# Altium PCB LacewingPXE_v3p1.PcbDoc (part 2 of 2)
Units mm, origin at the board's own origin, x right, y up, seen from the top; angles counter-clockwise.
Board outline 62.74 x 108.59 mm, 2 copper layers (Top Layer, Bottom Layer); 114 components, 91 nets, 539 pads, 84 vias.
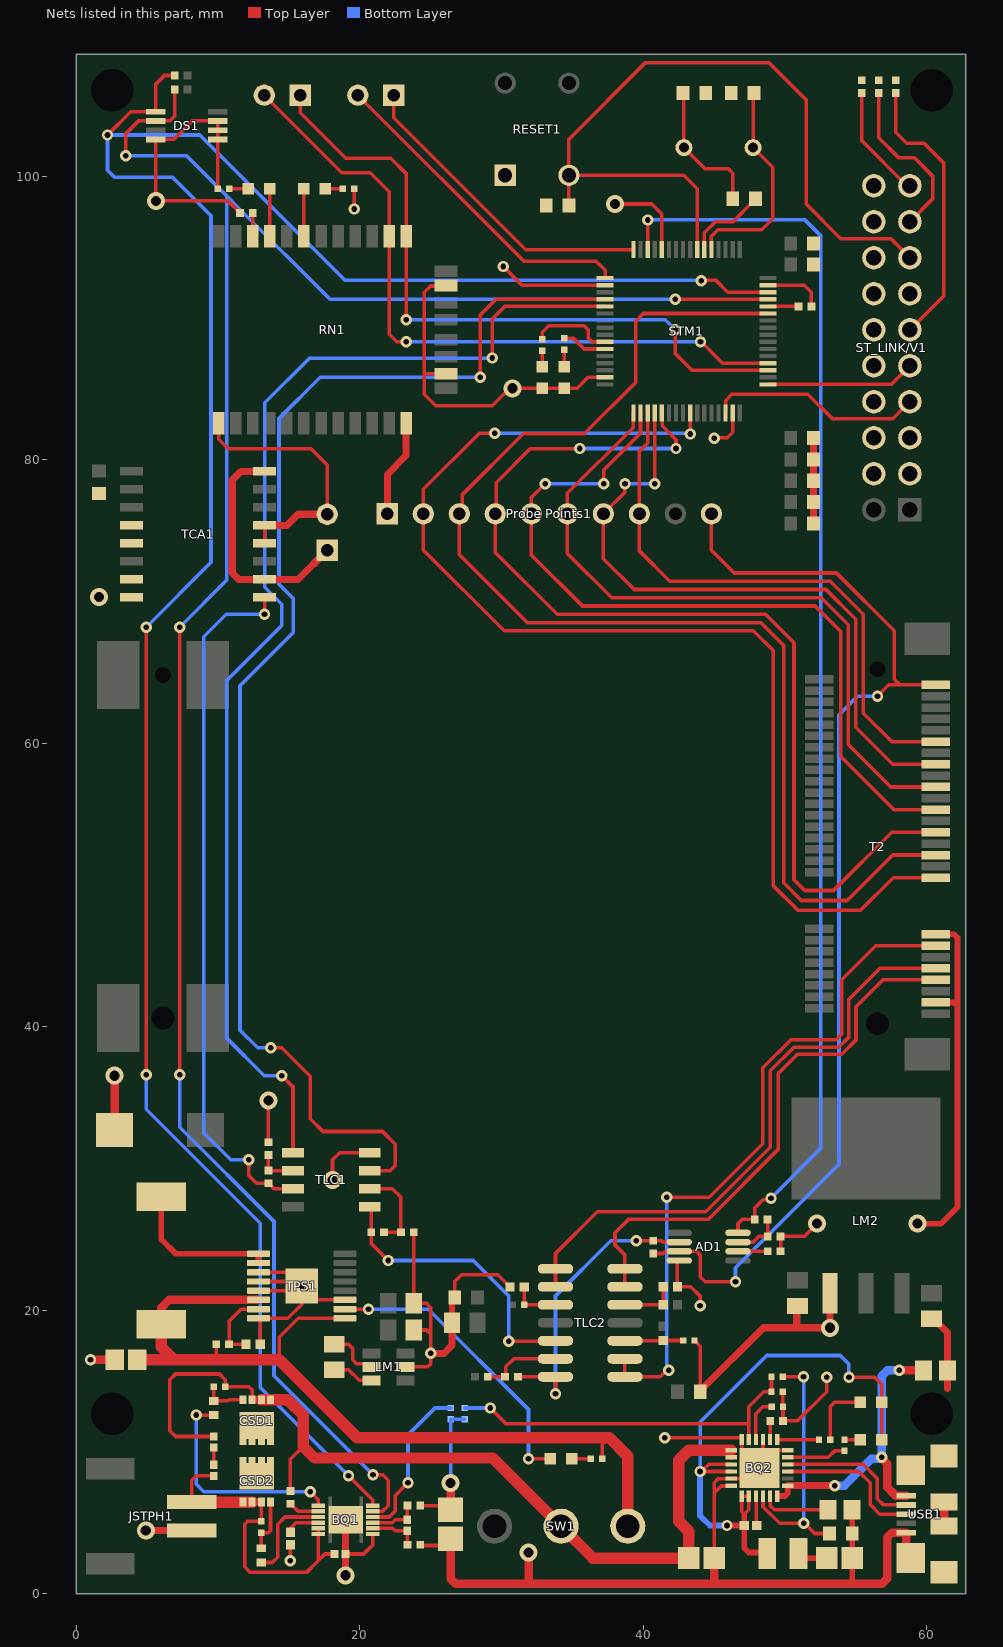
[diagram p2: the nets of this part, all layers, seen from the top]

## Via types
v1: diameter 0.8, hole 0.4, Top Layer to Bottom Layer, 66 vias
v2: diameter 1.27, hole 0.711, Top Layer to Bottom Layer, 18 vias

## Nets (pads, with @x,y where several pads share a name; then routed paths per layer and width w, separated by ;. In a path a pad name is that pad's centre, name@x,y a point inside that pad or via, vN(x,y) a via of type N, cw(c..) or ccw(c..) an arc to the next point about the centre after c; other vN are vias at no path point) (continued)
BAT+: BQ1.11 BQ1.12 C2.2 C11.1 CSD2.1 CSD2.2 CSD2.3 JSTPH1.1 R14.2 | length 23.1
  Top Layer w0.254: JSTPH1.1@8.149,6.461 8.149,8 8.459,8.31 C11.1@9.7,8.31 ; CSD2.3@13.05,6.461 R14.2@13.05,5.1 12.077,5.1 11.877,4.9 11.877,1.896 12.273,1.5 16.241,1.5 17.075,2.334 ; BQ1.11@17.075,4.613 BQ1.12@17.075,4.213 17.075,2.334 ; C2.2@18.21,2.8 17.541,2.8 17.075,2.334
  Top Layer w0.5: CSD2.2@12.4,6.461 CSD2.3@13.05,6.461
  Top Layer w0.8: JSTPH1.1@8.149,6.461 CSD2.1@11.75,6.461 CSD2.2@12.4,6.461
BAT-: BQ1.1 BQ1.13 C1.1 C2.1 JSTPH1.2 R1.2 R3.1 R6.1 R7.2 | length 20.9
  Top Layer w0.254: v1(15.1,2.334) C1.1@15.1,3.46 ; C2.1@18.99,2.8 20.265,2.8 20.925,3.46 BQ1.1@20.925,4.213 ; BQ1.13@18.99,5.203 BQ1.13@19,5.213 ; R6.1@24.255,6.213 26.112,6.213 R1.2@26.4,5.925
  Top Layer w0.5: v2(4.9,4.461) JSTPH1.2@8.149,4.461 ; BQ1.13@18.99,5.203 C2.1@18.99,2.8 19,2.79 v2(19,1.3)
  Top Layer w0.6: R1.2@26.4,5.925 v2(26.4,7.822)
  Bottom Layer w0.254: v2(26.4,7.822) R3.1@26.4,12.3 R7.2@27.4,12.3
BQ_SYS: BQ2.15 BQ2.16 BQ2.19 BQ2.20 C8.2 L1.1 PG.A STAT.A | length 41.9
  Top Layer w0.254: v1(44,8.622) v1@44.105,8.622 ; BQ2.16@46.188,8.622 v1@44.105,8.622 ; BQ2.15@46.188,9.122 44.605,9.122 v1@44.105,8.622 ; v1(54.5,15.266) 56.3,15.266 56.81,14.756 PG.A@56.81,13.5 STAT.A@56.81,10.872 ; 46.938,5.791 BQ2.19@46.938,6.872 BQ2.20@47.438,6.872 47.438,5.931 47.118,5.611 46.938,5.791
  Top Layer w0.4: v1(45.9,4.811) C8.2@47.118,4.811 ; 47.118,5.611 C8.2@47.118,4.811 ; L1.1@48.738,2.836 48.672,2.902 47.438,2.902 47.118,3.222 C8.2@47.118,4.811
  Bottom Layer w0.254: v1(44,8.622) 44,12.1 48.7,16.8 53.888,16.8 54.5,16.188 v1(54.5,15.266)
  Bottom Layer w0.4: v1(44,8.622) 44,5.5 44.689,4.811 v1(45.9,4.811)
GND: "Probe Points1.1" AD1.4 BQ2.6 BQ2.9 BQ2.12 BQ2.17 BQ2.18 BQ2.25 C4.2 C5.1 C6.1 C7.1 C9.1 C12.1 C13.2 C14.1 C15.2 C16.1 C18.2 C19.2 C20.1 C21.1 C22.1 C23.2 C24.2 C25.2 C26.2 C27.2 C28.2 C29.2 C30.2 C31.2 C32.2 D1.C D2.C DS1.4 DS1.5 DS1.6 DS1.7 LM1.2 LM2.1 Peltier1.2 R1.1 R2.1 R4.1 R5.1 R9.1 R18.1 R21.1 R22.1 R24.1 R26.1 R27.1 R28.1 R29.1 R39.1 R40.1 R41.1 R44.1 R46.1 R47.1 R48.1 RESET1.1 RN1.1 RN1.12 RN1.28 RN1.29 ST_LINK/V1.3 ST_LINK/V1.4 ST_LINK/V1.5 ST_LINK/V1.6 ST_LINK/V1.8 ST_LINK/V1.10 ST_LINK/V1.12 ST_LINK/V1.13 ST_LINK/V1.14 ST_LINK/V1.16 ST_LINK/V1.18 ST_LINK/V1.20 STM1.12 STM1.18 STM1.31 STM1.47 STM1.63 T2.3 T2.15 TCA1.4 TCA1.5 TCA1.7 TCA1.8 TCA1.12 TCA1.13 TLC1.4 TPS1.3 TPS1.4 TPS1.5 TPS1.8 TPS1.11 TPS1.PowerPAD USB1.5 USB1.6 USB1.7 USB1.8 USB1.9 USB1.10 USB1.11 | length 297.3
  Top Layer w0.254: R46.1@9.984,99.1 DS1.5@9.984,102.584 DS1.6@9.984,103.234 DS1.7@9.984,103.884 9.976,103.892 8.2,103.892 6.892,102.584 DS1.4@5.616,102.584 v2(5.616,98.243) 10.707,98.243 R48.1@11.55,97.4 ; RN1.1@10.059,82.552 10.059,81.423 10.719,80.764 16.558,80.764 17.7,79.621 Peltier1.2@17.7,76.14 ; TPS1.8@12.85,19.425 14.925,19.425 15.9,20.4 15.9,21.625 16.8,20.725 TPS1.11@18.95,20.725 ; TPS1.5@12.85,21.375 15.575,21.375 v1(15.9,21.7) TPS1.PowerPAD@15.575,22.025 ; TPS1.4@12.85,22.025 TPS1.PowerPAD@15.575,22.025 ; TPS1.3@12.85,22.675 14.925,22.675 TPS1.PowerPAD@15.575,22.025 ; R18.1@12.97,17.6 TPS1.8@12.97,19.327 ; TCA1.12@13.28,74.09 TCA1.13@13.28,75.36 ; R22.1@13.551,31.85 v2(13.551,34.793) ; v2(18.073,29.187) 18.073,30.6 18.578,31.105 TLC1.4@20.712,31.105 ; v1(19.6,97.673) R47.1@19.6,99.1 ; LM1.2@23.223,16 24.791,16 24.999,16.208 v1(24.999,16.95) 24.999,18.299 25,18.3 ; R21.1@23.798,25.5 23.798,20.502 C14.1@23.8,20.5 24.675,20.5 25,20.175 25,18.3 ; C16.1@23.8,18.6 24.7,18.6 25,18.3 ; R5.1@24.255,3.46 24.315,3.4 25.925,3.4 R1.1@26.4,3.875 ; RN1.29@26.082,86.052 24.552,86.052 ; RN1.28@26.082,92.276 26.044,92.238 24.999,92.238 24.552,91.791 24.552,86.052 ; C22.1@26.7,20.9 26.7,22.025 27.175,22.5 29.725,22.5 R27.1@30.6,21.625 ; v1(30.123,93.62) 31.443,92.3 STM1.18@37.3,92.3 ; STM1.31@37.3,85.8 36.1,85.8 35.326,85.026 D2.C@34.418,85.026 D1.C@32.863,85.026 v2(30.756,85.026) 30.57,85.026 29.335,83.792 25.363,83.792 24.552,84.603 24.552,86.052 ; v2(38.008,98.026) 40.591,98.026 41.3,97.317 STM1.12@41.3,94.8 ; v1(41.502,11) 46.915,11 46.938,10.977 BQ2.12@46.938,10.872 46.938,10.122 BQ2.25@48.188,8.872 ; AD1.4@42.524,23.5 42.491,23.5 42.4,23.409 R29.1@42.4,21.65 43.35,21.65 44,21 v1(44,20.3) ; R28.1@43.605,17.861 44.004,17.461 44.004,14.291 C21.1@44.004,14.241 ; C4.2@45,2.511 45,7.1 ; v1(45,81.5) 45.034,81.534 45.912,81.534 46.3,81.922 STM1.47@46.3,83.3 ; BQ2.18@46.188,7.622 46.166,7.6 45.5,7.6 45,7.1 ; BQ2.9@48.438,10.872 BQ2.25@48.438,9.122 ; STM1.63@48.8,92.3 51.35,92.3 51.85,91.8 R44.1@51.85,90.8 ; R24.1@49.676,24.15 R26.1@49.676,25.2 51.337,25.2 v2(52.237,26.1) ; R4.1@49.838,14.247 49.844,14.241 49.844,13.199 R9.1@49.849,13.193 ; R9.1@49.849,13.193 R2.1@49.85,12.19 50.872,12.19 52.928,14.245 v1(52.928,15.266) ; BQ2.6@50.188,10.122 49.438,10.122 BQ2.25@48.438,9.122 ; ST_LINK/V1.8@56.261,84.074 ST_LINK/V1.8@56.57,84.074 ; USB1.6@58.539,2.511 USB1.6@58.864,2.511 ; 45,7.1 45,7.822 45.3,8.122 BQ2.17@46.188,8.122 47.438,8.122 BQ2.25@48.188,8.872 ; BQ2.25@48.188,8.872 BQ2.25@48.438,9.122
  Top Layer w0.4: C13.2@26.5,19.1 26.5,20.7 C22.1@26.7,20.9 ; 54.728,0.7 C7.1@54.728,2.511 C5.1@54.728,4.25 C6.1@54.728,5.925 ; v2(59.346,26.1) 60.999,26.1 62.161,27.262 62.161,41.471 ; T2.15@60.603,46.494 T2.15@60.615,46.505 61.927,46.505 62.161,46.271 62.161,41.471 ; T2.3@60.615,41.705 61.927,41.705 62.161,41.471
  Top Layer w0.5: TCA1.13@13.28,75.36 14.87,75.36 15.65,76.14 Peltier1.2@17.7,76.14 ; 21.94,76.172 21.94,78.954 23.263,80.277 RN1.12@23.263,82.552 ; v1(24.999,16.95) 25.925,16.95 26.5,17.525 C13.2@26.5,19.1 ; C21.1@44.004,14.291 48.472,18.759 50.816,18.759 ; C19.2@50.872,20.3 50.816,20.244 50.816,18.759 ; C26.2@52,75.494 C27.2@52,77 C28.2@52,78.5 C29.2@52,80 C30.2@52,81.53 ; LM2.1@53.16,21.2 v2(53.16,18.759) 50.816,18.759 ; C18.2@60.325,19.4 60.475,19.4 61.45,18.425 C9.1@61.45,15.752 61.45,14.462
  Top Layer w0.6: v1(1,16.5) C12.1@2.7,16.5 ; v2(2.7,36.537) 2.702,36.535 C15.2@2.702,32.693 ; R1.1@26.4,3.875 26.4,1.051 26.751,0.7 31.9,0.7 ; v2(31.9,2.902) 31.9,0.7 ; C4.2@45,2.511 45,0.7 ; USB1.6@58.539,2.511 USB1.5@58.539,4.311 57.544,4.311 57.193,3.96 57.193,1.051 56.841,0.7 54.728,0.7 45,0.7 ; USB1.8@61.214,4.761 USB1.9@61.214,6.461 ; 31.9,0.7 45,0.7
  other v2: 1.6,70.3
I2C_SCL: BQ1.5 DS1.2 R32.1 STM1.61 | length 163.7
  Top Layer w0.254: v1(3.5,101.425) 3.5,103 4.384,103.884 DS1.2@5.616,103.884 6.6,103.884 6.95,104.234 R32.1@6.95,106.092 ; v1(7.296,36.603) v1(7.296,68.18) ; BQ1.5@20.925,5.813 21.6,5.813 22,6.213 22,8.006 21.623,8.383 21.029,8.383 v1(20.925,8.383) ; v1(42.251,91.3) STM1.61@48.8,91.3
  Bottom Layer w0.254: v1(3.5,101.425) 7.775,101.425 ; v1(7.296,36.603) 7.296,32.904 13.944,26.256 13.944,15.364 v1(20.925,8.383) ; v1(7.296,68.18) 10.6,71.484 10.6,98.6 ; v1(42.251,91.3) 17.9,91.3 11.5,97.7 ; 7.775,101.425 10.6,98.6 ; 7.775,101.425 10.6,98.6 ; 10.6,98.6 11.5,97.7 ; 10.6,98.6 11.5,97.7
I2C_SDA: BQ1.6 DS1.1 R31.1 STM1.62 | length 169.5
  Top Layer w0.254: v1(2.2,102.894) 3.84,104.534 DS1.1@5.616,104.534 5.616,106.492 6.216,107.092 R31.1@6.95,107.092 ; v1(4.934,36.603) v1(4.934,68.18) ; v1(19.2,8.31) 20.925,6.585 BQ1.6@20.925,6.213 ; v1(44.075,92.61) 44.123,92.658 45.092,92.658 45.95,91.8 STM1.62@48.8,91.8
  Bottom Layer w0.254: v1(4.934,36.603) 4.934,34.166 12.97,26.13 12.97,14.54 v1(19.2,8.31) ; v1(4.934,68.18) 9.5,72.746 9.5,97.2 6.777,99.923 2.677,99.923 2.2,100.4 v1(2.2,102.894) 8.706,102.894 18.942,92.658 44.026,92.658 v1(44.075,92.61)
IREF_ADC: AD1.8 R33.2 STM1.14 | length 88.3
  Top Layer w0.254: STM1.14@40.3,94.8 v1(40.3,96.901) ; AD1.8@46.674,25.45 46.674,26.1 46.974,26.4 R33.2@47.85,26.4 47.85,27.212 48.436,27.798 48.893,27.798 v1(48.998,27.902)
  Bottom Layer w0.254: v1(40.3,96.901) 51.399,96.901 52.5,95.8 52.5,31.405 v1(48.998,27.902)
NetAD1_6: AD1.6 R24.2 | length 2.1
  Top Layer w0.254: AD1.6@46.674,24.15 R24.2@48.776,24.15
NetAD1_7: AD1.7 R26.2 R33.1 | length 3.5
  Top Layer w0.254: AD1.7@46.674,24.8 47.738,24.8 48.138,25.2 R26.2@48.776,25.2 48.763,25.213 48.763,26.387 R33.1@48.75,26.4
NetBQ1_2: BQ1.2 C3.1 R5.2 | length 3.5
  Top Layer w0.254: BQ1.2@20.925,4.613 22.32,4.613 22.5,4.433 23.348,4.433 C3.1@23.35,4.435 23.353,4.433 23.353,3.463 R5.2@23.355,3.46
NetBQ1_3: BQ1.3 C3.2 R6.2 | length 3.5
  Top Layer w0.254: BQ1.3@20.925,5.013 22.295,5.013 22.5,5.218 23.348,5.218 C3.2@23.35,5.215 23.353,5.218 23.353,6.211 R6.2@23.355,6.213
NetBQ1_4: BQ1.4 R3.2 | length 11.3
  Top Layer w0.254: BQ1.4@20.925,5.413 22.077,5.413 22.5,5.836 22.5,6.922 v1(23.4,7.822)
  Bottom Layer w0.254: v1(23.4,7.822) 23.4,11.2 25.3,13.1 R3.2@26.4,13.1
NetBQ1_7: BQ1.7 R10.1 | length 15.6
  Top Layer w0.254: v1(8.459,12.6) R10.1@9.7,12.6 ; v1(16.5,7.2) 17.075,6.625 BQ1.7@17.075,6.213
  Bottom Layer w0.254: v1(8.459,12.6) 8.459,7.741 9,7.2 v1(16.5,7.2)
NetBQ1_8: BQ1.8 R12.1 | length 2.2
  Top Layer w0.254: R12.1@15.1,6.35 15.637,5.813 BQ1.8@17.075,5.813
NetBQ1_9: BQ1.9 R11.1 | length 6.7
  Top Layer w0.254: R11.1@13.05,2.2 13.827,2.2 14.204,2.577 14.204,4.9 14.717,5.413 BQ1.9@17.075,5.413
NetBQ1_10: BQ1.10 C1.2 | length 2.4
  Top Layer w0.254: C1.2@15.1,4.34 15.1,4.613 15.5,5.013 BQ1.10@17.075,5.013
NetBQ2_1: BQ2.1 BQ2.24 C9.2 USB1.1 | length 21.5
  Top Layer w0.4: BQ2.24@49.438,6.897 49.988,6.897 50.188,7.097 BQ2.1@50.188,7.622
  Top Layer w0.5: BQ2.1@50.188,7.622 v1(53.488,7.622) ; v1@56.81,9.562 v1(56.81,9.622)
  Top Layer w0.6: v1@56.81,9.562 57.193,9.179 57.193,7.518 57.8,6.911 USB1.1@58.539,6.911 ; v1(58.052,15.752) C9.2@59.75,15.752
  Bottom Layer w0.254: v1@56.706,9.518 v1(56.81,9.622)
  Bottom Layer w0.6: v1(53.488,7.622) 54.188,7.622 56.084,9.518 v1@56.706,9.518 ; v1(56.81,9.622) 56.81,15.362 57.2,15.752 v1(58.052,15.752)
NetBQ2_5: BQ2.5 R15.1 | length 4.2
  Top Layer w0.254: BQ2.5@50.188,9.622 53.038,9.622 53.488,10.072 R15.1@54.188,10.072
NetBQ2_7: BQ2.7 R16.1 | length 3
  Top Layer w0.254: BQ2.7@49.438,10.872 R16.1@52.388,10.872
NetBQ2_8: BQ2.8 R2.2 | length 1.3
  Top Layer w0.254: BQ2.8@48.938,10.872 48.944,10.878 48.944,12.184 R2.2@48.95,12.19 ; R2.2@48.944,12.194 R2.2@48.95,12.2
NetBQ2_10: BQ2.10 R9.2 | length 3.1
  Top Layer w0.254: BQ2.10@47.938,10.872 47.938,12.7 48.431,13.193 R9.2@49.049,13.193
NetBQ2_11: BQ2.11 R4.2 R7.1 R8.1 | length 25.9
  Top Layer w0.254: v1(29.2,13.1) 30.3,12 47.438,12 ; BQ2.11@47.438,10.872 47.438,12 ; R8.1@49.038,15.3 R4.2@49.038,14.247 48.492,14.247 47.438,13.193 47.438,12
  Bottom Layer w0.254: R7.1@27.4,13.1 v1(29.2,13.1)
NetBQ2_21: BQ2.21 C8.1 | length 2.1
  Top Layer w0.254: BQ2.21@47.938,6.872 47.961,6.849 47.961,4.848 C8.1@47.998,4.811
NetBQ2_22: BQ2.22 C5.2 R8.2 | length 18
  Top Layer w0.254: BQ2.22@48.438,6.872 48.438,6.142 49.619,4.961 v1(51.308,4.961) 51.383,4.961 52.094,4.25 C5.2@53.128,4.25 ; R8.2@49.838,15.3 v1(51.3,15.3)
  Bottom Layer w0.254: v1(51.3,15.3) 51.308,15.292 v1(51.308,4.961)
NetBQ2_23: BQ2.23 C6.2 | length 4.9
  Top Layer w0.254: BQ2.23@48.938,6.872 48.938,6.213 49.226,5.925 C6.2@53.028,5.925
NetC7_2: C7.2 L1.2 | length 2.1
  Top Layer w0.254: L1.2@50.938,2.836 L1.2@51.263,2.511
  Top Layer w0.4: L1.2@51.263,2.511 C7.2@52.928,2.511
NetC10_2: C10.2 C11.2 | length 1.2
  Top Layer w0.254: C11.2@9.7,9.09 C10.2@9.7,10.31
NetC17_1: C17.1 LM1.5 | length 3.8
  Top Layer w0.254: C17.1@18.2,17.6 19.2,17.6 19.5,17.3 19.5,16.5 19.792,16.208 20.615,16.208 LM1.5@20.823,16
NetC17_2: C17.2 LM1.6 | length 2.9
  Top Layer w0.254: C17.2@18.2,15.8 19.2,15.8 19.95,15.05 LM1.6@20.823,15.05
NetC24_1: C24.1 R45.1 X1.2 | length 9.9
  Top Layer w0.254: C24.1@42.8,105.85 42.86,105.79 X1.2@42.86,102 44.36,100.5 46,100.5 46.3,100.2 R45.1@46.3,98.4
NetC25_1: C25.1 STM1.5 X1.1 | length 15.3
  Top Layer w0.254: STM1.5@44.8,94.8 44.8,95.756 45.244,96.2 48.351,96.2 49.133,96.982 49.133,100.607 X1.1@47.74,102 47.74,105.79 C25.1@47.8,105.85
NetCONNECT_A: CONNECT.A RN1.19 | length 3.3
  Top Layer w0.254: CONNECT.A@16.05,99.1 16.05,95.765 RN1.19@16.059,95.756
NetCONNECT_C: CONNECT.C R47.2 | length 1.2
  Top Layer w0.254: CONNECT.C@17.562,99.1 R47.2@18.8,99.1
NetCSD1_4: CSD1.4 R10.2 R13.1 | length 3.1
  Top Layer w0.254: R13.1@9.7,14.6 R10.2@9.7,13.6 10.692,13.6 10.775,13.683 11.747,13.683 CSD1.4@11.75,13.68
NetCSD1_5: CSD1.5 CSD1.6 CSD1.7 CSD1.8 CSD1.9 CSD2.5 CSD2.6 CSD2.7 CSD2.8 CSD2.9 | length 0
  Top Layer w0.254: CSD2.7@12.381,9.441 CSD2.7@12.403,9.463
NetCSD2_4: CSD2.4 R11.2 R14.1 | length 3.8
  Top Layer w0.254: R11.2@13.05,3.2 R14.1@13.05,4.3 13.551,4.3 13.7,4.449 CSD2.4@13.7,6.461
NetD1_A: D1.A R42.1 | length 1.1
  Top Layer w0.254: D1.A@32.863,86.538 R42.1@32.863,87.681
NetD2_A: D2.A R43.1 | length 1.2
  Top Layer w0.254: D2.A@34.418,86.538 R43.1@34.418,87.742
NetL2_2: L2.2 TPS1.1 TPS1.2 | length 10.9
  Top Layer w0.4: L2.2@6,28 6,24.985 7.01,23.975 TPS1.1@12.85,23.975 TPS1.2@12.85,23.325
NetLOW_A: LOW.A R17.2 | length 1.3
  Top Layer w0.254: LOW.A@34.95,9.518 R17.2@36.3,9.518
NetLOW_C: LOW.C TPS1.10 | length 20.9
  Top Layer w0.254: TPS1.10@18.95,20.075 v1(20.615,20.075) ; v1(31.9,9.518) LOW.C@33.438,9.518
  Bottom Layer w0.254: v1(20.615,20.075) 24.825,20.075 31.9,13 v1(31.9,9.518)
NetPG_C: PG.C R16.2 | length 4.6
  Top Layer w0.254: R16.2@53.188,10.872 53.188,13.2 53.488,13.5 PG.C@55.298,13.5
NetR15_2: R15.2 STAT.C | length 1.1
  Top Layer w0.254: R15.2@54.188,10.872 STAT.C@55.298,10.872
NetR18_2: R18.2 R19.2 TPS1.7 | length 5.2
  Top Layer w0.254: R18.2@11.97,17.6 R19.2@10.775,17.6 10.775,19.227 11.623,20.075 TPS1.7@12.85,20.075
NetR21_2: R21.2 R25.1 TLC1.2 | length 6.1
  Top Layer w0.254: TLC1.2@20.712,28.565 20.72,28.557 22.295,28.557 22.898,27.955 R21.2@22.898,25.5 R25.1@21.7,25.5
NetR22_2: R22.2 R23.1 TLC1.6 | length 2.8
  Top Layer w0.254: R22.2@13.551,30.95 R23.1@13.551,29.85 13.559,29.843 15.28,29.843 TLC1.6@15.288,29.835
NetR37_1: R37.1 R38.2 TLC2.13 | length 5.7
  Top Layer w0.254: R38.2@29.028,15.3 R37.1@30.25,15.3 30.3,15.35 30.3,16 30.87,16.57 TLC2.13@33.8,16.57
NetR39_2: R39.2 ST_LINK/V1.19 | length 8.1
  Top Layer w0.254: R39.2@55.4,105.85 55.4,102.5 58.586,99.314 ST_LINK/V1.19@58.801,99.314
NetR40_2: R40.2 ST_LINK/V1.17 | length 12
  Top Layer w0.254: R40.2@56.6,105.85 56.6,102.7 58,101.3 59.1,101.3 60.4,100 60.4,98.373 ST_LINK/V1.17@58.801,96.774
NetR41_2: R41.2 ST_LINK/V1.11 | length 19.8
  Top Layer w0.254: R41.2@57.8,105.85 57.8,103.086 58.586,102.3 59.8,102.3 61.2,100.9 61.2,91.553 ST_LINK/V1.11@58.801,89.154
NetR42_2: R42.2 STM1.26 | length 5.9
  Top Layer w0.254: R42.2@32.863,88.481 32.863,88.972 33.327,89.436 35.818,89.436 36.1,89.154 36.1,88.6 36.4,88.3 STM1.26@37.3,88.3
NetR43_2: R43.2 STM1.27 | length 3.2
  Top Layer w0.254: R43.2@34.418,88.542 35.079,88.542 35.821,87.8 STM1.27@37.3,87.8
NetR44_2: R44.2 STM1.60 | length 2.1
  Top Layer w0.254: STM1.60@48.8,90.8 R44.2@50.95,90.8
NetR45_2: R45.2 STM1.6 | length 5.8
  Top Layer w0.254: STM1.6@44.3,94.8 44.3,95.989 45.085,96.774 46.324,96.774 47.9,98.35 R45.2@47.9,98.4
NetR46_2: R46.2 STATE.C | length 1.4
  Top Layer w0.254: R46.2@10.784,99.1 STATE.C@12.138,99.1
NetR48_2: R48.2 RN1.22 | length 1.6
  Top Layer w0.254: R48.2@12.45,97.4 12.45,95.765 RN1.22@12.459,95.756
NetRN1_21: RN1.21 STATE.A | length 3.3
  Top Layer w0.254: STATE.A@13.65,99.1 13.65,95.765 RN1.21@13.659,95.756
NRST: C23.1 RESET1.3 ST_LINK/V1.15 STM1.7 | length 54.7
  Top Layer w0.254: C23.1@34.75,97.927 RESET1.3@34.75,100.05 ; STM1.7@43.8,94.8 43.8,99.1 42.85,100.05 RESET1.3@34.75,100.05 ; ST_LINK/V1.15@58.801,94.234 57.468,95.567 53.933,95.567 51.5,98 51.5,105.351 48.851,108 40.15,108 34.75,102.6 RESET1.3@34.75,100.05
PACK+: BQ2.13 BQ2.14 C4.1 C10.1 CSD1.1 CSD1.2 CSD1.3 R12.2 R13.2 SW1.2 | length 66.5
  Top Layer w0.254: C10.1@9.7,11.09 7.01,11.09 6.6,11.5 6.6,15.1 7,15.5 10.1,15.5 10.5,15.1 R13.2@10.5,14.6 12.165,14.6 12.403,14.362 12.403,13.683 CSD1.3@12.4,13.68 ; R12.2@15.1,7.25 15.1,9.482 16,10.382
  Top Layer w0.4: BQ2.14@46.188,9.622 BQ2.13@46.188,10.122
  Top Layer w0.5: CSD1.3@12.4,13.68 CSD1.2@13.05,13.68
  Top Layer w0.8: CSD1.2@13.05,13.68 CSD1.1@13.7,13.68 14.92,13.68 16,12.6 16,10.382 16.814,9.568 29.378,9.568 SW1.2@34.205,4.742 ; SW1.2@34.2,4.674 34.225,4.614 ccw(c34.677,4.802) SW1.2@34.331,4.455 ; SW1.2@34.2,4.761 SW1.2@34.205,4.742 ; BQ2.13@46.188,10.122 43.205,10.122 42.5,9.417 42.5,5.112 43.205,4.408 C4.1@43.205,2.511 36.435,2.511 SW1.2@34.205,4.742
SPI_MISO: "Probe Points1.8" STM1.35 T2.41 | length 40.5
  Top Layer w0.254: STM1.35@40.3,83.3 40.3,81.171 39.72,80.591 39.72,76.172 39.72,73.547 41.85,71.417 53.183,71.417 55.509,69.091 55.509,62.105 57.509,60.105 T2.41@60.615,60.105
SPI_MOSI: "Probe Points1.7" STM1.36 T2.37 | length 46.9
  Top Layer w0.254: v1(38.7,78.3) 38.7,77.692 37.18,76.172 37.18,73 39.347,70.833 52.886,70.833 54.982,68.737 54.982,61.117 57.594,58.505 T2.37@60.615,58.505 ; v1(40.8,78.3) STM1.36@40.8,83.3
  Bottom Layer w0.254: v1(38.7,78.3) v1(40.8,78.3)
SPI_SCK: "Probe Points1.5" STM1.34 T2.29 | length 56.8
  Top Layer w0.254: v1(33.073,78.3) 32.1,77.327 32.1,76.172 32.1,73.267 35.7,69.667 52.128,69.667 53.927,67.868 53.927,59.06 57.682,55.305 T2.29@60.615,55.305 ; v1(37.2,78.3) 37.2,79.264 39.8,81.864 STM1.34@39.8,83.3
  Bottom Layer w0.254: v1(33.073,78.3) v1(37.2,78.3)
SPI_SS: "Probe Points1.6" STM1.33 T2.33 | length 49.6
  Top Layer w0.254: STM1.33@39.3,83.3 39.277,83.277 39.277,82.25 34.64,77.613 34.64,76.172 34.64,73.376 37.766,70.25 52.55,70.25 54.455,68.345 54.455,59.905 57.455,56.905 T2.33@60.615,56.905
SWCLK: ST_LINK/V1.9 STM1.49 | length 10.5
  Top Layer w0.254: STM1.49@48.8,85.3 57.487,85.3 ST_LINK/V1.9@58.801,86.614
SWDIO: ST_LINK/V1.7 STM1.46 | length 15.3
  Top Layer w0.254: STM1.46@45.8,83.3 45.8,84.156 46.244,84.6 51.601,84.6 53.334,82.867 57.594,82.867 ST_LINK/V1.7@58.801,84.074
TTN_CLK: "Probe Points1.4" STM1.37 T2.25 | length 74
  Top Layer w0.254: v1(35.504,80.776) 35.492,80.764 32.008,80.764 29.617,78.373 29.617,76.229 29.56,76.172 29.56,73.441 33.917,69.083 48.609,69.083 50.623,67.07 50.623,50.355 51.377,49.6 53.404,49.6 57.509,53.705 T2.25@60.615,53.705 ; STM1.37@41.3,83.3 41.323,83.277 41.323,82.377 42.3,81.4 v1(42.3,80.776)
  Bottom Layer w0.254: v1(35.504,80.776) v1(42.3,80.776)
TTN_PWM: "Probe Points1.3" STM1.59 T2.21 | length 88.6
  Top Layer w0.254: STM1.59@48.8,90.3 39.986,90.3 39.451,89.765 39.451,85.44 35.821,81.81 31.517,81.81 27.21,77.503 27.21,76.362 27.02,76.172 27,76.192 27,73.317 31.817,68.5 48.281,68.5 49.898,66.882 49.898,50.144 ; 49.9,50.144 51.144,48.9 54.389,48.9 57.594,52.105 T2.21@60.615,52.105
TTN_ready: "Probe Points1.2" STM1.41 T2.17 | length 83.6
  Top Layer w0.254: v1(29.509,81.864) 28.444,81.864 24.48,77.9 24.48,76.172 24.48,73.62 30.184,67.916 47.761,67.916 49.174,66.503 49.174,49.926 50.9,48.2 55.316,48.2 57.621,50.505 T2.17@60.615,50.505 ; v1(43.295,81.805) 43.3,81.81 STM1.41@43.3,83.3
  Bottom Layer w0.254: v1(29.509,81.864) 43.236,81.864 v1(43.295,81.805)
UART_RX: RN1.14 STM1.52 UART1.2 | length 49.3
  Top Layer w0.254: UART1.2@13.26,105.7 18.735,100.225 20.726,100.225 22.069,98.883 RN1.14@22.069,95.756 22.069,88.831 22.6,88.3 v1(23.263,88.3) ; v1(44.026,88.3) 44.085,88.3 45.585,86.8 STM1.52@48.8,86.8
  Bottom Layer w0.254: v1(23.263,88.3) v1(44.026,88.3)
UART_TX: RN1.13 STM1.51 UART1.1 | length 48.8
  Top Layer w0.254: UART1.1@15.8,105.7 15.8,104.469 19.015,101.254 22.186,101.254 23.263,100.177 RN1.13@23.263,95.756 v1(23.263,89.863) ; v1(42.26,89.154) 42.26,87.469 43.429,86.3 STM1.51@48.8,86.3
  Bottom Layer w0.254: v1(23.263,89.863) 41.551,89.863 v1(42.26,89.154)
USART_RX: STM1.17 UART2.2 | length 23.1
  Top Layer w0.254: UART2.2@19.86,105.7 31.56,94 36.644,94 37.3,93.344 STM1.17@37.3,92.8
USART_TX: STM1.16 UART2.1 | length 22.3
  Top Layer w0.254: UART2.1@22.4,105.7 22.4,104.108 31.708,94.8 STM1.16@39.3,94.8
USB_D+: BQ2.3 USB1.3 | length 10.5
  Top Layer w0.254: BQ2.3@50.188,8.622 55.2,8.622 56,7.822 56,6.293 56.682,5.611 USB1.3@58.539,5.611
USB_D-: BQ2.4 USB1.2 | length 10.4
  Top Layer w0.254: BQ2.4@50.188,9.122 55.5,9.122 56.5,8.122 56.5,6.7 56.939,6.261 USB1.2@58.539,6.261
VBAT: C12.2 L2.1 R17.1 R19.1 SW1.1 TPS1.6 TPS1.9 | length 63
  Top Layer w0.254: 9.875,16.5 R19.1@9.875,17.6 ; 14.314,16.5 14.314,18.081 15.658,19.425 TPS1.9@18.95,19.425 ; R17.1@37.1,9.518 37.1,10.5 37.6,11
  Top Layer w0.6: L2.1@6,19 6,20.175 6.55,20.725 TPS1.6@12.85,20.725
  Top Layer w0.8: C12.2@4.3,16.5 6.9,16.5 ; L2.1@6,19 6,17.4 6.9,16.5 ; SW1.1@38.9,4.761 38.9,9.7 37.6,11 19.814,11 14.314,16.5 9.875,16.5 6.9,16.5
Vcharge: R29.2 R36.1 TLC2.5 | length 4
  Top Layer w0.254: TLC2.5@38.7,20.38 R36.1@41.405,20.38 41.405,21.65 R29.2@41.4,21.65
Vcharge_buf: T2.7 TLC2.6 TLC2.7 | length 38.6
  Top Layer w0.254: TLC2.6@38.7,21.65 TLC2.7@38.7,22.92 38.7,23.896 38,24.596 38,25.45 38.95,26.4 44.574,26.4 49.5,31.326 49.5,36.677 50.878,38.055 54,38.055 55,39.055 55,41.405 56.9,43.305 T2.7@60.615,43.305
Vdac: R28.2 R35.1 TLC2.3 | length 4.1
  Top Layer w0.254: TLC2.3@38.7,17.84 38.71,17.85 41.39,17.85 R35.1@41.4,17.861 R28.2@42.804,17.861
Vdac_buf: T2.13 TLC2.1 TLC2.2 | length 48.5
  Top Layer w0.254: TLC2.2@38.7,16.57 TLC2.1@38.7,15.3 41.2,15.3 41.652,15.752 v1(41.8,15.752) ; v1(41.652,27.955) 44.655,27.955 48.431,31.731 48.431,37.093 50.418,39.08 53.606,39.08 54,39.474 54,43.305 56.4,45.705 T2.13@60.615,45.705
  Bottom Layer w0.254: v1(41.652,27.955) 41.652,15.9 v1(41.8,15.752)
VDAC_electrode: STM1.20 TLC1.3 | length 93.6
  Top Layer w0.254: v1(13.719,38.5) 14.5,38.5 16.5,36.5 16.5,33.5 17.4,32.6 21.6,32.6 22.5,31.7 22.5,30.202 22.133,29.835 TLC1.3@20.712,29.835 ; v1(28.5,85.8) 28.5,90.19 29.61,91.3 STM1.20@37.3,91.3
  Bottom Layer w0.254: v1(13.719,38.5) 12.8,38.5 11.549,39.751 11.549,64.049 15.3,67.8 15.3,70.2 14.3,71.2 14.3,82.9 17.2,85.8 v1(28.5,85.8)
VDAC_electrode_amp: R25.2 TLC1.1 TLC2.12 | length 20.4
  Top Layer w0.254: TLC1.1@20.712,27.295 20.8,27.207 R25.2@20.8,25.5 20.8,24.7 v1(22,23.5) ; v1(30.5,17.8) 33.76,17.8 TLC2.12@33.8,17.84
  Bottom Layer w0.254: v1(22,23.5) 28,23.5 30.5,21 v1(30.5,17.8)
VDAC_peltier: STM1.21 TLC1.5 | length 86.1
  Top Layer w0.254: v1(14.5,36.535) 15.288,35.747 TLC1.5@15.288,31.105 ; v1(29.343,87.159) 29.343,89.916 30.227,90.8 STM1.21@37.3,90.8
  Bottom Layer w0.254: v1(14.5,36.535) 13.265,36.535 10.6,39.2 10.6,64.4 14.5,68.3 14.5,69.8 13.3,71 13.3,84 16.459,87.159 v1(29.343,87.159)
VDAC_peltier_amp: R23.2 TCA1.9 TLC1.7 | length 49.7
  Top Layer w0.254: v1(12.165,30.6) 12.165,29.5 12.715,28.95 R23.2@13.551,28.95 13.944,28.557 15.28,28.557 TLC1.7@15.288,28.565 ; v1(13.28,69.083) TCA1.9@13.28,70.28
  Bottom Layer w0.254: v1(12.165,30.6) 10.9,30.6 9,32.5 9,67.5 10.583,69.083 v1(13.28,69.083)
Velectrode_buf: AD1.2 R30.2 R37.2 TLC2.14 | length 21.1
  Top Layer w0.254: R37.2@31.15,15.3 TLC2.14@33.8,15.3 v1(33.8,14.1) ; v1(39.5,24.9) R30.2@40.7,24.9 41.29,24.9 41.39,24.8 AD1.2@42.524,24.8
  Bottom Layer w0.254: v1(33.8,14.1) 33.8,21 37.7,24.9 v1(39.5,24.9)
Vpeltier_buf: Peltier1.1 TCA1.10 TCA1.16 | length 16.8
  Top Layer w0.5: TCA1.16@13.28,79.17 11.623,79.17 11,78.547 11,72.009 11.459,71.55 TCA1.10@13.28,71.55 15.65,71.55 Peltier1.1@17.7,73.6
VREF_electrode: "Probe Points1.10" AD1.3 R30.1 T2.51 | length 80.2
  Top Layer w0.254: R30.1@40.7,24 41.39,24 41.502,24.112 42.486,24.112 AD1.3@42.524,24.15 43.746,24.15 44,23.896 44,22.355 44.355,22 v1(46.5,22) ; 44.8,76.172 44.8,73.6 46.4,72 53.616,72 57.7,67.916 57.7,64.505 58.1,64.105 ; v1(56.515,63.305) 57.315,64.105 58.1,64.105 ; T2.51@60.615,64.105 58.1,64.105
  Bottom Layer w0.254: v1(46.5,22) 46.5,23 53.8,30.3 53.8,62 55.105,63.305 v1(56.515,63.305)
Vtemp: R27.2 R34.1 TLC2.10 | length 3.5
  Top Layer w0.254: R27.2@31.6,21.625 31.594,21.619 31.594,20.386 R34.1@31.588,20.38 TLC2.10@33.8,20.38
Vtemp_buf: T2.9 TLC2.8 TLC2.9 | length 42.2
  Top Layer w0.254: TLC2.9@33.8,21.65 TLC2.8@33.8,22.92 33.8,24 36.74,26.94 44.39,26.94 48.95,31.5 48.95,36.882 50.623,38.555 53.791,38.555 54.5,39.264 54.5,41.924 56.681,44.105 T2.9@60.615,44.105
pads on no net: BQ1.14 BQ1.15 BQ1.16 BQ1.17 BQ2.2 DS1.3 JSTPH1.MP1 JSTPH1.MP2 RESET1.2 RESET1.4 RN1.2 RN1.3 RN1.4 RN1.5 RN1.6 RN1.7 RN1.8 RN1.9 RN1.10 RN1.15 RN1.16 RN1.17 RN1.18 RN1.20 RN1.23 RN1.24 RN1.30 RN1.31 RN1.32 RN1.33 RN1.34 RN1.35 STM1.2 STM1.3 STM1.4 STM1.8 STM1.9 STM1.10 STM1.11 STM1.15 STM1.22 STM1.23 STM1.24 STM1.25 STM1.28 STM1.29 STM1.30 STM1.38 STM1.39 STM1.40 STM1.42 STM1.43 STM1.44 STM1.45 STM1.50 STM1.53 STM1.54 STM1.55 STM1.56 STM1.57 STM1.58 SW1.3 T1.MH3 T1.MH4 T1.MP1L T1.MP2L T1.MP3L T1.MP4L T2.2 T2.4 T2.5 T2.6 T2.8 T2.10 T2.11 T2.12 T2.14 T2.16 T2.18 T2.19 T2.20 T2.22 T2.23 T2.24 T2.26 T2.27 T2.28 T2.30 T2.31 T2.32 T2.34 T2.35 T2.36 T2.38 T2.39 T2.40 T2.42 T2.43 T2.44 T2.46 T2.47 T2.48 T2.50 T2.52 T2.MH1 T2.MH2 T2.MP1C T2.MP2C TCA1.2 TCA1.3 TCA1.6 TCA1.11 TCA1.14 TCA1.15 TPS1.12 USB1.4

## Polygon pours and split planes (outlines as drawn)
GND on Bottom Layer "GND_L02_P122" (solid, pour order 122): 62.224,69.612 62.224,39.142 50,39.142 50,69.614 49.9,69.614
GND on Bottom Layer "GND_L02_P121" (solid, pour order 121): 30.966,27.9 19,27.9 19,14.657 31.001,14.657
GND on Bottom Layer "GND_L02_P118" (solid, pour order 118): 30.5,0.5 62.5,0.5 62.5,39.5 50,39.5 50,27.955 30.5,27.955
GND on Bottom Layer "GND_L02_P119" (solid, pour order 119): 0.5,69.55 12.5,69.55 12.5,36 19.601,36 19.601,14.54 0.514,14.54
GND on Bottom Layer "GND_L02_P115" (solid, pour order 115): 0.5,108 0.5,69 62.2,69 62.2,108
BAT- on Bottom Layer "BAT-_L02_P111" (solid, pour order 111): 0.5,0.5 0.5,7 22,7 22,9 27.5,9 27.5,0.5
no net on Bottom Layer "NONET_L02_P105" (solid, pour order 105): 0.127,0.127
no net on Bottom Layer "Bottom Layer-No Net 1" (solid, pour order 54): 18.923,81.534
no net on Bottom Layer "Bottom Layer-No Net 2" (solid, pour order 0): -30.861,61.214
GND on Top Layer "GND_L01_P116" (solid, pour order 116): 0.5,79.2 7,79.2 7,69.083 0.5,69.083
GND on Top Layer "GND_L01_P114" (solid, pour order 114): 27.6,108.6 27.6,96.5 51.5,96.5 51.5,73.3 62.8,73.3 62.8,108.6
GND on Top Layer "GND_L01_P113" (solid, pour order 113): 57.8,16.5 57.8,0.254 62.5,0.254 62.5,16.5
NetCSD1_5 on Top Layer "NETCSD1_5_L01_P107" (solid, pour order 107): 10.5,12.9 10.5,7.2 14.5,7.2 14.5,12.9
no net on Top Layer "NONET_L01_P103" (solid, pour order 103): 16.637,37.719
no net on Top Layer "NONET_L01_P096" (solid, pour order 96): 28.448,23.18
no net on Top Layer "NONET_L01_P095" (solid, pour order 95): 19.052,19.517
no net on Top Layer "NONET_L01_P094" (solid, pour order 94): 17.653,18.867
no net on Top Layer "Top Layer-No Net" (solid, pour order 40): 13.081,78.74
no net on Top Layer "Top Layer-No Net 1" (solid, pour order 30): 11.303,35.179
no net on Top Layer "Top Layer-No Net 2" (solid, pour order 16): 62.738,17.018
no net on Top Layer "Top Layer-No Net 3" (solid, pour order 4): 0,108.585
no net on Top Layer "Top Layer-No Net 4" (solid, pour order 2): -0.127,108.839

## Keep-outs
Keep-Out Layer:
  lines w0.5: 19.188,64.705 19.188,40.672 43.188,40.672 43.188,64.705 19.377,64.705 ; 0,0 62.738,0 62.738,108.585 0,108.585 0,0

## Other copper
Top Layer:
  pour cut-out: 0.5,81.5 5.1,81.5
  pour cut-out: 45.5,38.5 45.5,67 17,67 17,38.5
Bottom Layer:
  pour cut-out: 19.601,36 19.601,32.5 16.366,32.5 16.366,36
  pour cut-out: 0.5,97 9.5,97 9.5,81 0.5,81
  pour cut-out: 0.5,95.9

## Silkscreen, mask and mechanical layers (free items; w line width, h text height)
Top Overlay:
  drawing of 6186 lines, arcs and shapes, not listed
  text "Tx" at 21.882,107.22 h0.6
  text "Rx" at 12.7,107.2 h0.6
  text "Tx" at 15.3,107.2 h0.6
  text "Rx" at 19.3,107.2 h0.6
  text "SS" at 34.64,72.9 h0.6 r90
  text "GND" at 21.94,72.3 h0.6 r90
  text "RDY" at 24.48,72.3 h0.6 r90
  text "PWM" at 27.02,72.3 h0.6 r90
  text "TCK" at 29.617,72.3 h0.6 r90
  text "SCK" at 32.1,72.3 h0.6 r90
  text "MOSI" at 37.18,71.9 h0.6 r90
  text "MISO" at 39.72,71.8 h0.6 r90
  text "3.3V" at 42.3,71.8 h0.6 r90
  text "VREF" at 44.8,71.7 h0.6 r90
  text "Jan 2020" at 29.074,31.964 h0.8
  text "Lacewing PXE v3.1" at 29.074,30.44 h0.8
  text "For clinical trials" at 29.111,28.86 h0.8
  text "+5VDD" at 20,12 h0.8
  text "VBAT" at 20.7,10.554 h0.8
  text "PACK+" at 20.7,9.122 h0.8
  text "CHR" at 28.1,8.6 h1
  text "PWR" at 37.8,8.6 h1

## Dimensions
0,108.585 to 0,0 on Mechanical 1
0,0 to 62.738,0 on Mechanical 1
